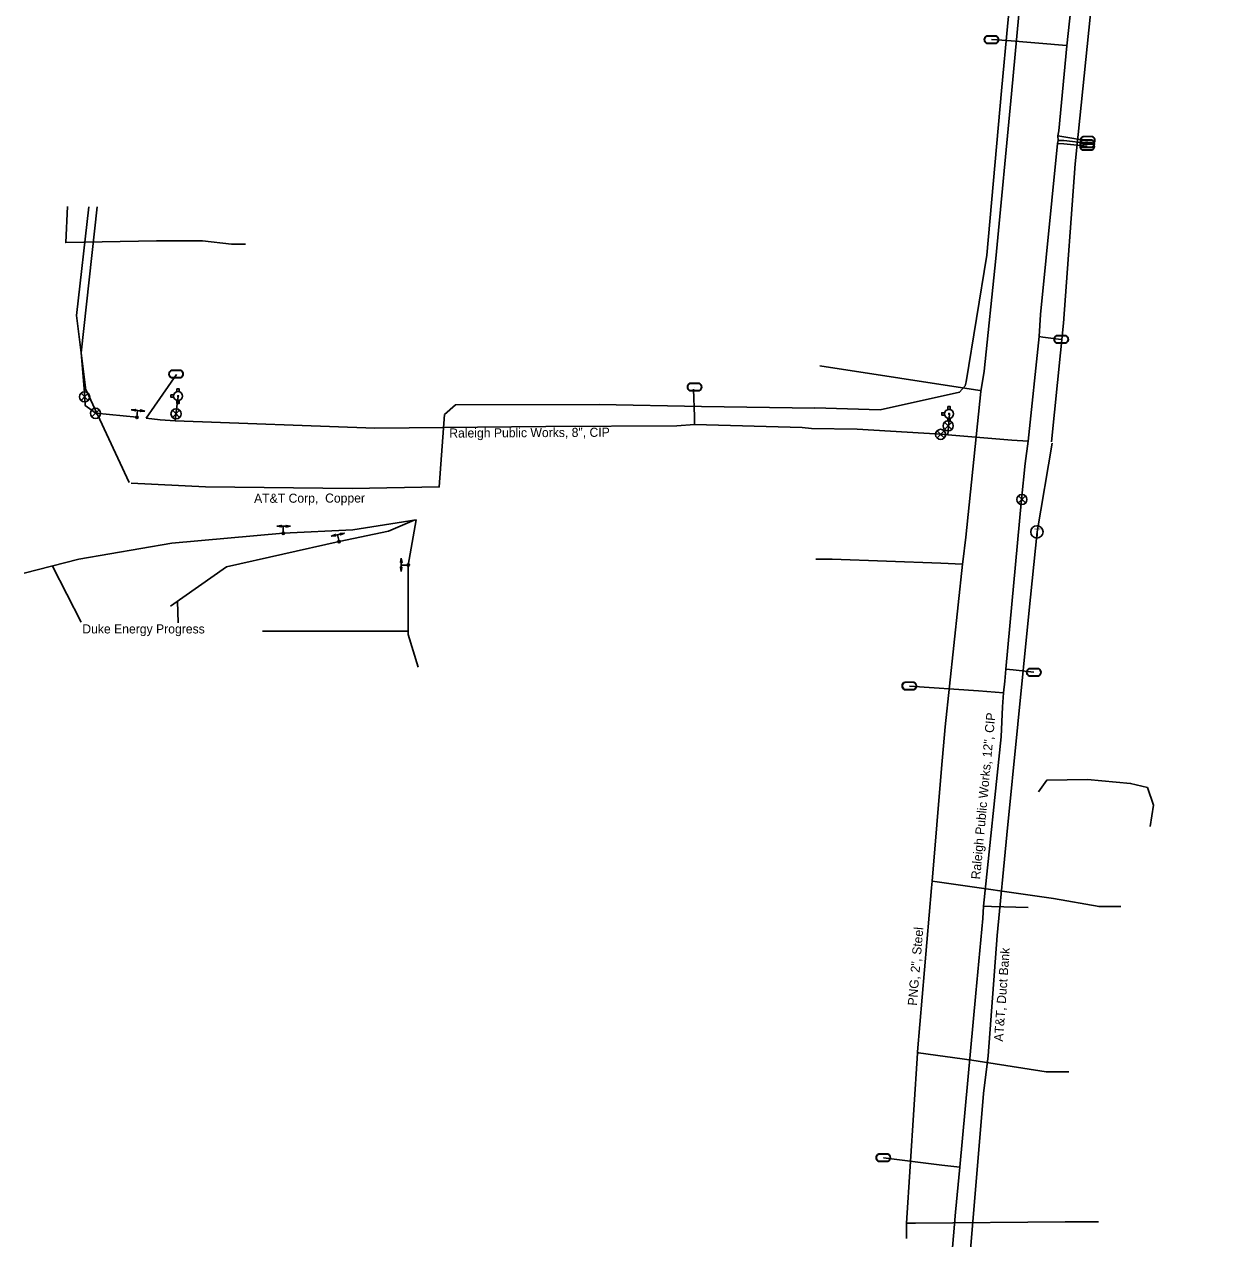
# Model space of a CAD drawing. Extents: x 2070721 to 2083340, y 729290 to 737883.
# Drawn here: x 2081990 to 2082520, y 736705 to 737239 of the extents above; entities that cross this region are included whole.
import ezdxf

# ---------------------------------------------------------------- set-up
doc = ezdxf.new("R2010")
doc.units = 0
for name, color, linetype in [('Exist Utilities Gas UG Line SUE LOS B', 7, 'Continuous'), ('Exist Utilities Gas UG Line SUE LOS B Text', 7, 'Continuous'), ('Exist Utilities Power Change of Service SUE CELL', 7, 'Continuous'), ('Exist Utilities Power UG Cable SUE LOS B', 7, 'Continuous'), ('Exist Utilities Power UG Cable SUE LOS C', 7, 'Continuous'), ('Exist Utilities Power UG Cable SUE LOS C Leader', 7, 'Continuous'), ('Exist Utilities Power UG Cable SUE LOS C Text', 7, 'Continuous'), ('Exist Utilities Telephone Manhole CELL', 7, 'Continuous'), ('Exist Utilities Telephone UG Cable SUE LOS C', 7, 'Continuous'), ('Exist Utilities Telephone UG Cable SUE LOS C Text', 7, 'Continuous'), ('Exist Utilities Telephone UG Conduit SUE LOS B', 7, 'Continuous'), ('Exist Utilities Telephone UG FO SUE LOS B Text', 7, 'Continuous'), ('Exist Utilities Water Change of Service SUE CELL', 7, 'Continuous'), ('Exist Utilities Water Fire Hydrant CELL', 7, 'Continuous'), ('Exist Utilities Water Meter CELL', 7, 'Continuous'), ('Exist Utilities Water UG Line SUE LOS B', 7, 'Continuous'), ('Exist Utilities Water UG Line SUE LOS B Text', 7, 'Continuous'), ('Exist Utilities Water Valve CELL', 7, 'Continuous')]:
    doc.layers.add(name, color=color, linetype=linetype)

msp = doc.modelspace()

# ---------------------------------------------------------------- linework, layer by layer
at = {"layer": 'Exist Utilities Gas UG Line SUE LOS B'}
for points in [[(2082410, 737077.78), (2082411.36, 737086.72), (2082416.51, 737136.35), (2082423.37, 737208.61), (2082428.12, 737259.46)], [(2082086.81, 737142.62), (2082080.65, 737142.62), (2082067.93, 737144.1), (2082047.64, 737144.1), (2082007.79, 737143.29), (2082008.6, 737159.16)], [(2082410.05, 737078.11), (2082409.57, 737078.19), (2082339.15, 737089.12)], [(2082410, 737077.78), (2082403.4, 737013.84), (2082401.98, 737003.02), (2082401.84, 737001.99)], [(2082401.84, 737001.99), (2082392.37, 737002.41), (2082344.59, 737004.1), (2082337.38, 737004.1)], [(2082401.84, 737001.99), (2082394.29, 736930.45), (2082392.69, 736912.07), (2082388.57, 736862.67), (2082388.2, 736859.67)], [(2082388.57, 736862.67), (2082390.79, 736862.35), (2082441.82, 736854.95), (2082461.89, 736851.41), (2082471.48, 736851.41)], [(2082388.2, 736859.67), (2082382.07, 736787.6), (2082382.04, 736786.95)], [(2082382.06, 736787.27), (2082382.54, 736787.14), (2082405.93, 736783.98), (2082438.62, 736778.77), (2082448.61, 736778.77)], [(2082382.04, 736786.95), (2082377.25, 736712.27), (2082377.25, 736705.53)], [(2082377.25, 736712.27), (2082381.16, 736712.31), (2082447.01, 736712.93), (2082461.69, 736712.93)]]:
    msp.add_lwpolyline(points, dxfattribs=at)
at = {"layer": 'Exist Utilities Power Change of Service SUE CELL'}
for p, q in [((2082106.48, 737018.6), (2082100.51, 737018.6)), ((2082103.34, 737015.52), (2082103.34, 737018.6)), ((2082103.34, 737018.6), (2082106.48, 737018.6)), ((2082103.34, 737015.52), (2082103.34, 737015.52)), ((2082130.31, 737015.54), (2082124.49, 737014.23)), ((2082127.25, 737014.85), (2082130.31, 737015.54)), ((2082127.92, 737011.84), (2082127.25, 737014.85)), ((2082127.92, 737011.84), (2082127.92, 737011.84)), ((2082155.22, 737001.5), (2082155.22, 737004.64)), ((2082155.22, 737004.64), (2082155.22, 736998.67)), ((2082158.3, 737001.5), (2082155.22, 737001.5)), ((2082158.3, 737001.5), (2082158.3, 737001.5))]:
    msp.add_line(p, q, dxfattribs=at)
for points in [[(2082100.51, 737018.6), (2082102.48, 737018.95), (2082102.06, 737018.6), (2082102.45, 737018.3)], [(2082106.48, 737018.6), (2082104.5, 737018.26), (2082104.92, 737018.6), (2082104.54, 737018.91)], [(2082124.49, 737014.23), (2082126.34, 737015), (2082126, 737014.57), (2082126.44, 737014.36)], [(2082130.31, 737015.54), (2082128.46, 737014.77), (2082128.79, 737015.2), (2082128.35, 737015.41)], [(2082155.22, 736998.67), (2082154.87, 737000.64), (2082155.22, 737000.22), (2082155.52, 737000.61)], [(2082155.22, 737004.64), (2082155.56, 737002.66), (2082155.22, 737003.08), (2082154.91, 737002.7)]]:
    msp.add_lwpolyline(points, close=True, dxfattribs=at)
for centre in [(2082103.34, 737015.52), (2082127.92, 737011.84), (2082158.3, 737001.5)]:
    msp.add_circle(centre, 0.517, dxfattribs=at)
at = {"layer": 'Exist Utilities Power UG Cable SUE LOS B'}
msp.add_line((2082161.82, 737021.41), (2082158.3, 737001.5), dxfattribs=at)
for points in [[(2082103.34, 737015.52), (2082133.96, 737017.04), (2082161.75, 737021.48)], [(2082160.93, 737021.21), (2082149.62, 737016.5), (2082127.92, 737011.84)], [(2082484.4, 736886.67), (2082485.88, 736896.06), (2082483.16, 736903.73), (2082475.75, 736905.58), (2082456.82, 736907.35), (2082438.93, 736906.94), (2082435.27, 736901.85)]]:
    msp.add_lwpolyline(points, dxfattribs=at)
at = {"layer": 'Exist Utilities Power UG Cable SUE LOS C'}
for points in [[(2081989.55, 736997.93), (2082013.53, 737004.14), (2082054.43, 737011.2), (2082103.34, 737015.52)], [(2082053.87, 736983.53), (2082078.41, 737000.75), (2082127.92, 737011.84)], [(2082158.3, 737001.5), (2082158.3, 736971.08), (2082162.61, 736956.68)]]:
    msp.add_lwpolyline(points, dxfattribs=at)
at = {"layer": 'Exist Utilities Power UG Cable SUE LOS C Leader'}
for p, q in [((2082001.89, 737001.08), (2082014.59, 736976.38)), ((2082056.94, 736985.67), (2082057.14, 736976.21)), ((2082158.14, 736972.49), (2082094.25, 736972.49))]:
    msp.add_line(p, q, dxfattribs=at)
at = {"layer": 'Exist Utilities Telephone Manhole CELL'}
msp.add_circle((2082434.58, 737016.09), 2.72, dxfattribs=at)
at = {"layer": 'Exist Utilities Telephone UG Cable SUE LOS C'}
for points in [[(2082403.44, 737082.03), (2082412.57, 737137.7), (2082418.97, 737209.91), (2082421.82, 737239.88), (2082432.43, 737345.64), (2082437.88, 737400.24), (2082446.55, 737496.08), (2082457.15, 737602.73), (2082463.04, 737658.16), (2082480.56, 737850.96), (2082483.62, 737882.51)], [(2082017.92, 737159), (2082012.49, 737111.23), (2082016.64, 737078.39), (2082016.82, 737078.34), (2082035.62, 737037.81)], [(2082337.01, 737070.62), (2082365.7, 737069.73), (2082400.6, 737077.49), (2082403.07, 737080.36), (2082403.44, 737082.03)], [(2082036.57, 737037.57), (2082069.13, 737035.95), (2082133.69, 737035.26), (2082171.93, 737035.92), (2082174.2, 737067.68), (2082179.11, 737071.93), (2082242.14, 737072.12), (2082287.24, 737071.24), (2082337.04, 737070.55)]]:
    msp.add_lwpolyline(points, dxfattribs=at)
at = {"layer": 'Exist Utilities Telephone UG Conduit SUE LOS B'}
for points in [[(2082440.99, 737055.64), (2082446.34, 737107.79), (2082451.46, 737177.85), (2082462.75, 737288.32), (2082470.03, 737364.09), (2082470.98, 737371.16), (2082477.18, 737429.09), (2082489.87, 737576.45), (2082501.4, 737701.55), (2082515.01, 737823.97), (2082519.76, 737879.1)], [(2082398.1, 736612.48), (2082411.1, 736769.26), (2082413.2, 736785.84), (2082417.08, 736838.79), (2082421.4, 736882.93), (2082431.06, 736980.24), (2082434.68, 737016.11), (2082441.24, 737055.15)]]:
    msp.add_lwpolyline(points, dxfattribs=at)
at = {"layer": 'Exist Utilities Water Change of Service SUE CELL'}
for p, q in [((2082042.46, 737069.23), (2082036.53, 737069.82)), ((2082039.04, 737066.47), (2082039.34, 737069.54)), ((2082039.04, 737066.47), (2082039.04, 737066.47)), ((2082039.34, 737069.54), (2082042.46, 737069.23))]:
    msp.add_line(p, q, dxfattribs=at)
for points in [[(2082036.53, 737069.82), (2082038.52, 737069.97), (2082038.07, 737069.67), (2082038.42, 737069.32)], [(2082042.46, 737069.23), (2082040.47, 737069.08), (2082040.92, 737069.39), (2082040.57, 737069.73)]]:
    msp.add_lwpolyline(points, close=True, dxfattribs=at)
msp.add_circle((2082039.04, 737066.47), 0.517, dxfattribs=at)
at = {"layer": 'Exist Utilities Water Fire Hydrant CELL'}
for p, q in [((2082057.16, 737075.79), (2082057.16, 737075.79)), ((2082395.99, 737068), (2082395.99, 737068))]:
    msp.add_line(p, q, dxfattribs=at)
for points in [[(2082055.25, 737076.3), (2082053.96, 737076.3), (2082053.96, 737075.28), (2082055.25, 737075.28)], [(2082056.65, 737077.7), (2082056.65, 737078.99), (2082057.67, 737078.99), (2082057.67, 737077.68)], [(2082056.65, 737073.88), (2082056.65, 737072.59), (2082057.67, 737072.59), (2082057.67, 737073.9)], [(2082395.48, 737069.92), (2082395.48, 737071.2), (2082396.5, 737071.2), (2082396.5, 737069.89)], [(2082394.08, 737068.52), (2082392.79, 737068.52), (2082392.79, 737067.49), (2082394.08, 737067.49)], [(2082395.48, 737066.09), (2082395.48, 737064.8), (2082396.5, 737064.8), (2082396.5, 737066.12)]]:
    msp.add_lwpolyline(points, dxfattribs=at)
for centre, radius in [((2082057.16, 737075.79), 1.98), ((2082057.16, 737075.79), 0.243), ((2082395.99, 737068), 1.98), ((2082395.99, 737068), 0.243)]:
    msp.add_circle(centre, radius, dxfattribs=at)
at = {"layer": 'Exist Utilities Water Meter CELL'}
for p, q in [((2082414.6, 737232.48), (2082414.6, 737232.48)), ((2082456.91, 737188.26), (2082456.91, 737188.26)), ((2082456.69, 737185.53), (2082456.69, 737185.53)), ((2082456.72, 737186.75), (2082456.72, 737186.75)), ((2082445.29, 737100.75), (2082445.29, 737100.75)), ((2082056.25, 737085.51), (2082056.25, 737085.51)), ((2082284.14, 737079.77), (2082284.14, 737079.77)), ((2082433.24, 736954.42), (2082433.24, 736954.42)), ((2082378.52, 736948.43), (2082378.52, 736948.43)), ((2082367.09, 736741.04), (2082367.09, 736741.04))]:
    msp.add_line(p, q, dxfattribs=at)
for points in [[(2082416.63, 737230.92), (2082412.53, 737230.92)], [(2082416.63, 737230.78), (2082412.53, 737230.78)], [(2082412.56, 737234.18), (2082416.63, 737234.18)], [(2082412.56, 737234.04), (2082416.63, 737234.04)], [(2082454.68, 737188.45), (2082458.76, 737188.45)], [(2082454.68, 737188.31), (2082458.76, 737188.31)], [(2082454.87, 737189.96), (2082458.95, 737189.96)], [(2082454.87, 737189.83), (2082458.95, 737189.83)], [(2082458.73, 737183.97), (2082454.63, 737183.97)], [(2082458.73, 737183.83), (2082454.63, 737183.83)], [(2082454.66, 737187.23), (2082458.73, 737187.23)], [(2082454.66, 737187.09), (2082458.73, 737187.09)], [(2082458.76, 737185.18), (2082454.66, 737185.18)], [(2082458.76, 737185.05), (2082454.66, 737185.05)], [(2082458.95, 737186.7), (2082454.85, 737186.7)], [(2082458.95, 737186.56), (2082454.85, 737186.56)], [(2082443.25, 737102.45), (2082447.33, 737102.45)], [(2082443.25, 737102.31), (2082447.33, 737102.31)], [(2082447.33, 737099.19), (2082443.23, 737099.19)], [(2082447.33, 737099.05), (2082443.23, 737099.05)], [(2082054.21, 737087.21), (2082058.29, 737087.21)], [(2082054.21, 737087.07), (2082058.29, 737087.07)], [(2082058.29, 737083.95), (2082054.19, 737083.95)], [(2082058.29, 737083.81), (2082054.19, 737083.81)], [(2082282.1, 737081.47), (2082286.18, 737081.47)], [(2082282.1, 737081.33), (2082286.18, 737081.33)], [(2082286.18, 737078.21), (2082282.08, 737078.21)], [(2082286.18, 737078.07), (2082282.08, 737078.07)], [(2082435.28, 736952.86), (2082431.18, 736952.86)], [(2082435.28, 736952.72), (2082431.18, 736952.72)], [(2082431.2, 736956.12), (2082435.28, 736956.12)], [(2082431.2, 736955.98), (2082435.28, 736955.98)], [(2082376.48, 736950.13), (2082380.56, 736950.13)], [(2082376.48, 736950), (2082380.56, 736950)], [(2082380.56, 736946.87), (2082376.46, 736946.87)], [(2082380.56, 736946.73), (2082376.46, 736946.73)], [(2082369.13, 736739.48), (2082365.03, 736739.48)], [(2082369.13, 736739.34), (2082365.03, 736739.34)], [(2082365.05, 736742.74), (2082369.13, 736742.74)], [(2082365.05, 736742.6), (2082369.13, 736742.6)]]:
    msp.add_lwpolyline(points, dxfattribs=at)
for centre, radius, start, end in [((2082413.29, 737232.47), 1.86, 113.178, 245.9794), ((2082413.3, 737232.47), 1.73, 115.3009, 243.7824), ((2082415.89, 737232.48), 1.86, 293.6483, 66.3084), ((2082415.9, 737232.48), 1.73, 295.1272, 64.8728), ((2082455.41, 737186.74), 1.86, 113.178, 245.9794), ((2082455.42, 737186.74), 1.73, 115.3009, 243.7824), ((2082455.6, 737188.26), 1.86, 113.178, 245.9794), ((2082455.61, 737188.26), 1.73, 115.3009, 243.7824), ((2082458.01, 737186.75), 1.86, 293.6483, 66.3084), ((2082458.02, 737186.75), 1.73, 295.1272, 64.8728), ((2082458.2, 737188.26), 1.86, 293.6483, 66.3084), ((2082458.22, 737188.26), 1.73, 295.1272, 64.8728), ((2082455.39, 737185.53), 1.86, 113.178, 245.9794), ((2082455.4, 737185.53), 1.73, 115.3009, 243.7824), ((2082457.99, 737185.53), 1.86, 293.6483, 66.3084), ((2082458, 737185.53), 1.73, 295.1272, 64.8728), ((2082443.98, 737100.74), 1.86, 113.178, 245.9794), ((2082443.99, 737100.74), 1.73, 115.3009, 243.7824), ((2082446.58, 737100.75), 1.86, 293.6483, 66.3084), ((2082446.59, 737100.75), 1.73, 295.1272, 64.8728), ((2082054.94, 737085.5), 1.86, 113.178, 245.9794), ((2082054.95, 737085.5), 1.73, 115.3009, 243.7824), ((2082057.54, 737085.51), 1.86, 293.6483, 66.3084), ((2082057.55, 737085.51), 1.73, 295.1272, 64.8728), ((2082282.83, 737079.76), 1.86, 113.178, 245.9794), ((2082282.84, 737079.76), 1.73, 115.3009, 243.7824), ((2082285.43, 737079.77), 1.86, 293.6483, 66.3084), ((2082285.44, 737079.77), 1.73, 295.1272, 64.8728), ((2082431.93, 736954.41), 1.86, 113.178, 245.9794), ((2082431.94, 736954.41), 1.73, 115.3009, 243.7824), ((2082434.53, 736954.42), 1.86, 293.6483, 66.3084), ((2082434.54, 736954.42), 1.73, 295.1272, 64.8728), ((2082377.21, 736948.43), 1.86, 113.178, 245.9794), ((2082377.22, 736948.43), 1.73, 115.3009, 243.7824), ((2082379.81, 736948.43), 1.86, 293.6483, 66.3084), ((2082379.82, 736948.43), 1.73, 295.1272, 64.8728), ((2082365.78, 736741.03), 1.86, 113.178, 245.9794), ((2082365.79, 736741.03), 1.73, 115.3009, 243.7824), ((2082368.38, 736741.04), 1.86, 293.6483, 66.3084), ((2082368.39, 736741.04), 1.73, 295.1272, 64.8728)]:
    msp.add_arc(centre, radius, start, end, dxfattribs=at)
at = {"layer": 'Exist Utilities Water UG Line SUE LOS B'}
msp.add_line((2082395.41, 737058.76), (2082396.16, 737068), dxfattribs=at)
for points in [[(2082443.82, 737190.2), (2082444.22, 737192.46), (2082447.74, 737229.76), (2082454.53, 737292.18)], [(2082414.68, 737232.54), (2082421.58, 737232.04), (2082447.56, 737229.86)], [(2082435.52, 737101.94), (2082436.16, 737111.62), (2082443.68, 737186.87), (2082443.92, 737188.12), (2082443.82, 737190.2)], [(2082443.82, 737190.2), (2082446.35, 737189.78), (2082456.88, 737188.05)], [(2082456.54, 737186.96), (2082446.46, 737188.11), (2082443.92, 737188.12)], [(2082443.68, 737186.87), (2082446.48, 737186.62), (2082456.71, 737185.63)], [(2082039.04, 737066.47), (2082020.95, 737068.25), (2082016.32, 737071.67), (2082016.09, 737075.58), (2082014.49, 737094.86), (2082021.55, 737158.93)], [(2082430.73, 737055.97), (2082435.52, 737101.94)], [(2082435.52, 737101.94), (2082437.12, 737101.74), (2082445.22, 737100.72)], [(2082043.13, 737066.04), (2082046.82, 737071.41), (2082056.38, 737085.32)], [(2082055.89, 737064.98), (2082056.36, 737068.94), (2082057.12, 737075.64)], [(2082284.15, 737063.3), (2082284.05, 737066.83), (2082283.7, 737078.9)], [(2082055.89, 737064.98), (2082049.25, 737065.33), (2082043.13, 737066.04)], [(2082055.89, 737064.98), (2082143.58, 737061.72), (2082218.78, 737062.44), (2082276.4, 737062.74), (2082284.15, 737063.3)], [(2082284.15, 737063.3), (2082331.37, 737061.93), (2082335.5, 737061.51)], [(2082335.5, 737061.51), (2082355.64, 737061.26), (2082392.26, 737059.03), (2082395.39, 737058.76), (2082423.61, 737056.45), (2082430.73, 737055.97)], [(2082421, 736955.83), (2082427.79, 737030.39), (2082429.41, 737046.22), (2082430.73, 737055.97)], [(2082419.94, 736945.35), (2082420.45, 736950.54), (2082421, 736955.83)], [(2082421, 736955.83), (2082424.1, 736955.42), (2082433.2, 736954.48)], [(2082419.94, 736945.35), (2082408.88, 736946.2), (2082378.56, 736948.3)], [(2082411.18, 736851.65), (2082418.88, 736926.06), (2082419.48, 736939.21), (2082419.94, 736945.35)], [(2082400.72, 736736.91), (2082407.72, 736813.44), (2082410.77, 736846.16), (2082411.18, 736851.65)], [(2082411.18, 736851.65), (2082414.7, 736851.47), (2082430.7, 736850.96)], [(2082400.72, 736736.91), (2082392.83, 736737.84), (2082367.14, 736740.99)], [(2082384.35, 736558.86), (2082384.46, 736561.59), (2082391.2, 736628.12), (2082394.55, 736666.82), (2082398.88, 736717.07), (2082400.72, 736736.91)]]:
    msp.add_lwpolyline(points, dxfattribs=at)
at = {"layer": 'Exist Utilities Water Valve CELL'}
for points in [[(2082017.65, 737077.06), (2082014.5, 737073.91), (2082016.07, 737075.48), (2082017.65, 737073.91), (2082014.5, 737077.06)], [(2082022.46, 737069.81), (2082019.3, 737066.66), (2082020.88, 737068.23), (2082022.46, 737066.66), (2082019.3, 737069.81)], [(2082057.81, 737069.57), (2082054.67, 737066.42), (2082056.24, 737067.99), (2082057.81, 737066.42), (2082054.67, 737069.57)], [(2082393.85, 737060.55), (2082390.7, 737057.4), (2082392.28, 737058.98), (2082393.85, 737057.4), (2082390.7, 737060.55)], [(2082397.16, 737064.34), (2082394.01, 737061.19), (2082395.59, 737062.77), (2082397.16, 737061.19), (2082394.01, 737064.34)], [(2082429.58, 737031.97), (2082426.43, 737028.82), (2082428, 737030.39), (2082429.58, 737028.82), (2082426.43, 737031.97)]]:
    msp.add_lwpolyline(points, dxfattribs=at)
for centre in [(2082016.07, 737075.48), (2082020.88, 737068.23), (2082056.24, 737067.99), (2082395.59, 737062.77), (2082392.28, 737058.98), (2082428, 737030.39)]:
    msp.add_circle(centre, 2.23, dxfattribs=at)

# ---------------------------------------------------------------- texts
at = {"layer": 'Exist Utilities Gas UG Line SUE LOS B Text'}
msp.add_text('PNG, 2", Steel', height=4, rotation=85.1413, dxfattribs=at).set_placement((2082381.78, 736807.77))
at = {"layer": 'Exist Utilities Power UG Cable SUE LOS C Text'}
msp.add_text('Duke Energy Progress', height=4, dxfattribs=at).set_placement((2082015.05, 736971.49))
at = {"layer": 'Exist Utilities Telephone Manhole CELL'}
msp.add_text('T', height=3.5, dxfattribs=at).set_placement((2082433.4, 737014.08))
at = {"layer": 'Exist Utilities Telephone UG Cable SUE LOS C Text'}
msp.add_text('AT&T Corp,  Copper', height=4, rotation=0.1727, dxfattribs=at).set_placement((2082090.55, 737028.88))
at = {"layer": 'Exist Utilities Telephone UG FO SUE LOS B Text'}
msp.add_text('AT&T, Duct Bank', height=4, rotation=85.8017, dxfattribs=at).set_placement((2082419.66, 736791.99))
at = {"layer": 'Exist Utilities Water UG Line SUE LOS B Text'}
for s, rotation, p in [('Raleigh Public Works, 8", CIP ', 0.2987, (2082176.32, 737057.56)), ('Raleigh Public Works, 12", CIP ', 84.6792, (2082409.6, 736863.27))]:
    msp.add_text(s, height=4, rotation=rotation, dxfattribs=at).set_placement(p)

doc.saveas('drawing.dxf')
